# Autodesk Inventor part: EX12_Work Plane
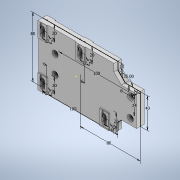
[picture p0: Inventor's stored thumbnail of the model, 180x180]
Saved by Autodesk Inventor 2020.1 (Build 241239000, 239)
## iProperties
Created: 2019-10
Part Number: EX12_Work Plane
Material: Generic
Document SubType Name: Modeling
Designer: Synergysoft Dell02
Density: 1 g/cm^3
Appearance: Default
Author: Synergysoft Dell02
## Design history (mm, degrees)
sketch "Sketch1"
  geometry: L1 (-50, -40)-(-50, 40); L2 (-50, 40)-(50, 40); L3 (50, 40)-(50, 30); L4 (50, 30)-(60, 20); L5 (60, 20)-(80, 20); L6 (80, 20)-(80, -20); L7 (80, -20)-(60, -20); L8 (60, -20)-(50, -30); L9 (50, -30)-(50, -40); L10 (50, -40)-(-50, -40); L11 (-50, 0)-(80, 0); L12 (-50, 40)-(-38, 40); L13 (-38, 40)-(-38, 20); L14 (-38, 20)-(-50, 20); L15 (-50, 20)-(-50, 40); L16 (-44, 34)-(-44, 26); L17 (-47, 34)-(-47, 26); L18 (-41, 26)-(-41, 34); L19 (12, 20)-(0, 20); L20 (6, 34)-(6, 26); L21 (3, 34)-(3, 26); L22 (9, 26)-(9, 34); L23 (12, 40)-(12, 20); L24 (0, 20)-(0, 40); L25 (0, 40)-(12, 40); L26 (-38, -40)-(-50, -40); L27 (-44, -26)-(-44, -34); L28 (-47, -26)-(-47, -34); L29 (-41, -34)-(-41, -26); L30 (-38, -20)-(-38, -40); L31 (-50, -40)-(-50, -20); L32 (-50, -20)-(-38, -20); L33 (44, -40)-(38.869, -40); L34 (38, -26)-(38, -34); L35 (35, -26)-(35, -34); L36 (41, -34)-(41, -26); L37 (44, -20)-(44, -40); L38 (32, -40)-(32, -20); L39 (32, -20)-(44, -20); C1 r 4 at (72, 12); C2 r 4 at (72, -12); C3 r 4 at (-28, 12); C4 r 4 at (-28, -12); A1 r 3 centre (-44, 34) between (-41, 34) and (-47, 34); A2 r 3 centre (-44, 26) between (-47, 26) and (-41, 26); A3 r 3 centre (6, 26) between (3, 26) and (9, 26); A4 r 3 centre (6, 34) between (9, 34) and (3, 34); A5 r 3 centre (-44, -34) between (-47, -34) and (-41, -34); A6 r 3 centre (-44, -26) between (-41, -26) and (-47, -26); A7 r 3 centre (38, -34) between (35, -34) and (41, -34); A8 r 3 centre (38, -26) between (41, -26) and (35, -26); 23 further points
  constraints: 86 end point, 16 point on circle, 16 tangent, 15 midpoint, 13 parallel, 12 centre point, 9 perpendicular, 6 horizontal, 6 horizontal alignment, 6 vertical, 5 point on line, 5 vertical alignment, 7 other
  dimensions: "d1" = 100 distance of L9.end L1.start; "d2" = 80 distance of L1.start L1.end; "d3" = 40 distance of L5.end L6.end; "d4" = 135 deg angle of L5 L4; "d6" = 80 distance from line of L6 point (0, 0); "d7" = 10 distance from line of L2 L3.end; "d10" = 12 distance of L13.end L14.end; "d11" = 20 distance of L12.end L13.end; "d12" = 8 distance of L16.start L16.end; "d13" = 3 radius of A2; "d14" = 12 distance of L19.start L19.end; "d15" = 20 distance of L23.start L19.start; "d16" = 8 distance of L20.start L20.end; "d17" = 3 radius of A3; "d18" = 12 distance of L26.start L26.end; "d19" = 20 distance of L30.start L26.start; "d20" = 8 distance of L27.start L27.end; "d21" = 3 radius of A5; "d23" = 20 distance of L37.start L33.start; "d24" = 8 distance of L34.start L34.end; "d25" = 3 radius of A7; "d26" = 6 distance from line of L20 point (0, 0); "d27" = 6 distance between parallel lines of L1 L27; "d31" = 12 distance between parallel lines of L37 L38; "d32" = 12 distance between parallel lines of L9 L34; "d37" = 8 diameter of C1; "d38" = 8 distance from line of L6 C1.centre; "d39" = 8 distance from line of L5 C1.centre; "d42" = 24 distance of C1.centre C2.centre; "d45" = 100 distance of C1.centre C3.centre
extrude "Extrusion1" new body sketch "Sketch1" stored distance "d8" = 10; taper "d9" = 0 deg
extrude "Extrusion3" join sketch "Sketch1" stored distance "d33" = 12; taper "d34" = 0 deg
extrude "Extrusion4" cut sketch "Sketch1" stored distance "d35" = 12; taper "d36" = 0 deg
sketch "Sketch2"
  geometry: 1 further point
extrude "Extrusion5" cut sketch "Sketch1" stored distance "d48" = 10; taper "d49" = 0 deg
body "Solid1"
